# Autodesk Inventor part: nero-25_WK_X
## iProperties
Shininess: 20.0
Length Units: 11269
Angle Units: 11279
Time Units: 11290
Mass Units: 11283
Length Display Precision: 2
Angle Display Precision: 2
Part Number: nero-25_WK_X
Material: Nichtrostender Stahl - 440C
Document SubType Name: Modellieren
Description: Ipc-25 /CXX/M18
Checked By: Alves
Created: 2005-08
Designer: Ohle
Manufacturer: Standard
Standards Organization: Custom
Density: 0.0
Volumn: 0.0
Area: 0.0
PropertySet Name: Model Information
Control State: 0
Master: False
Checked Out: False
BESTELLNUMMER: Ipc-25 /CXX/M18
ME: ST
Title: Ipc Sensoren
Author: Ohle
Comments: keine Bemerkung
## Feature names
1. Grundkörper pico+ [Revolution]
2. Pole [Extrusion]
3. Rundung Pole [Fillet]
4. Verdrehsicherung [Extrusion]
5. Bohrung Ausrichtung [Extrusion]
6. USW-Fläche Winkelkopf [Extrusion]
7. Extrusion6
8. Extrusion7
9. Extrusion8
